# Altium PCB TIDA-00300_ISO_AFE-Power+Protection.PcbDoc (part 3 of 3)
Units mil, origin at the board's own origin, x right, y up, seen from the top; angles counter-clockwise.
Board outline 3622.05 x 2204.8 mil, 4 copper layers (Top Layer, GND Layer, PWR Layer, Bottom Layer), stack 63.6 mil thick; 240 components, 107 nets, 584 pads, 225 vias.
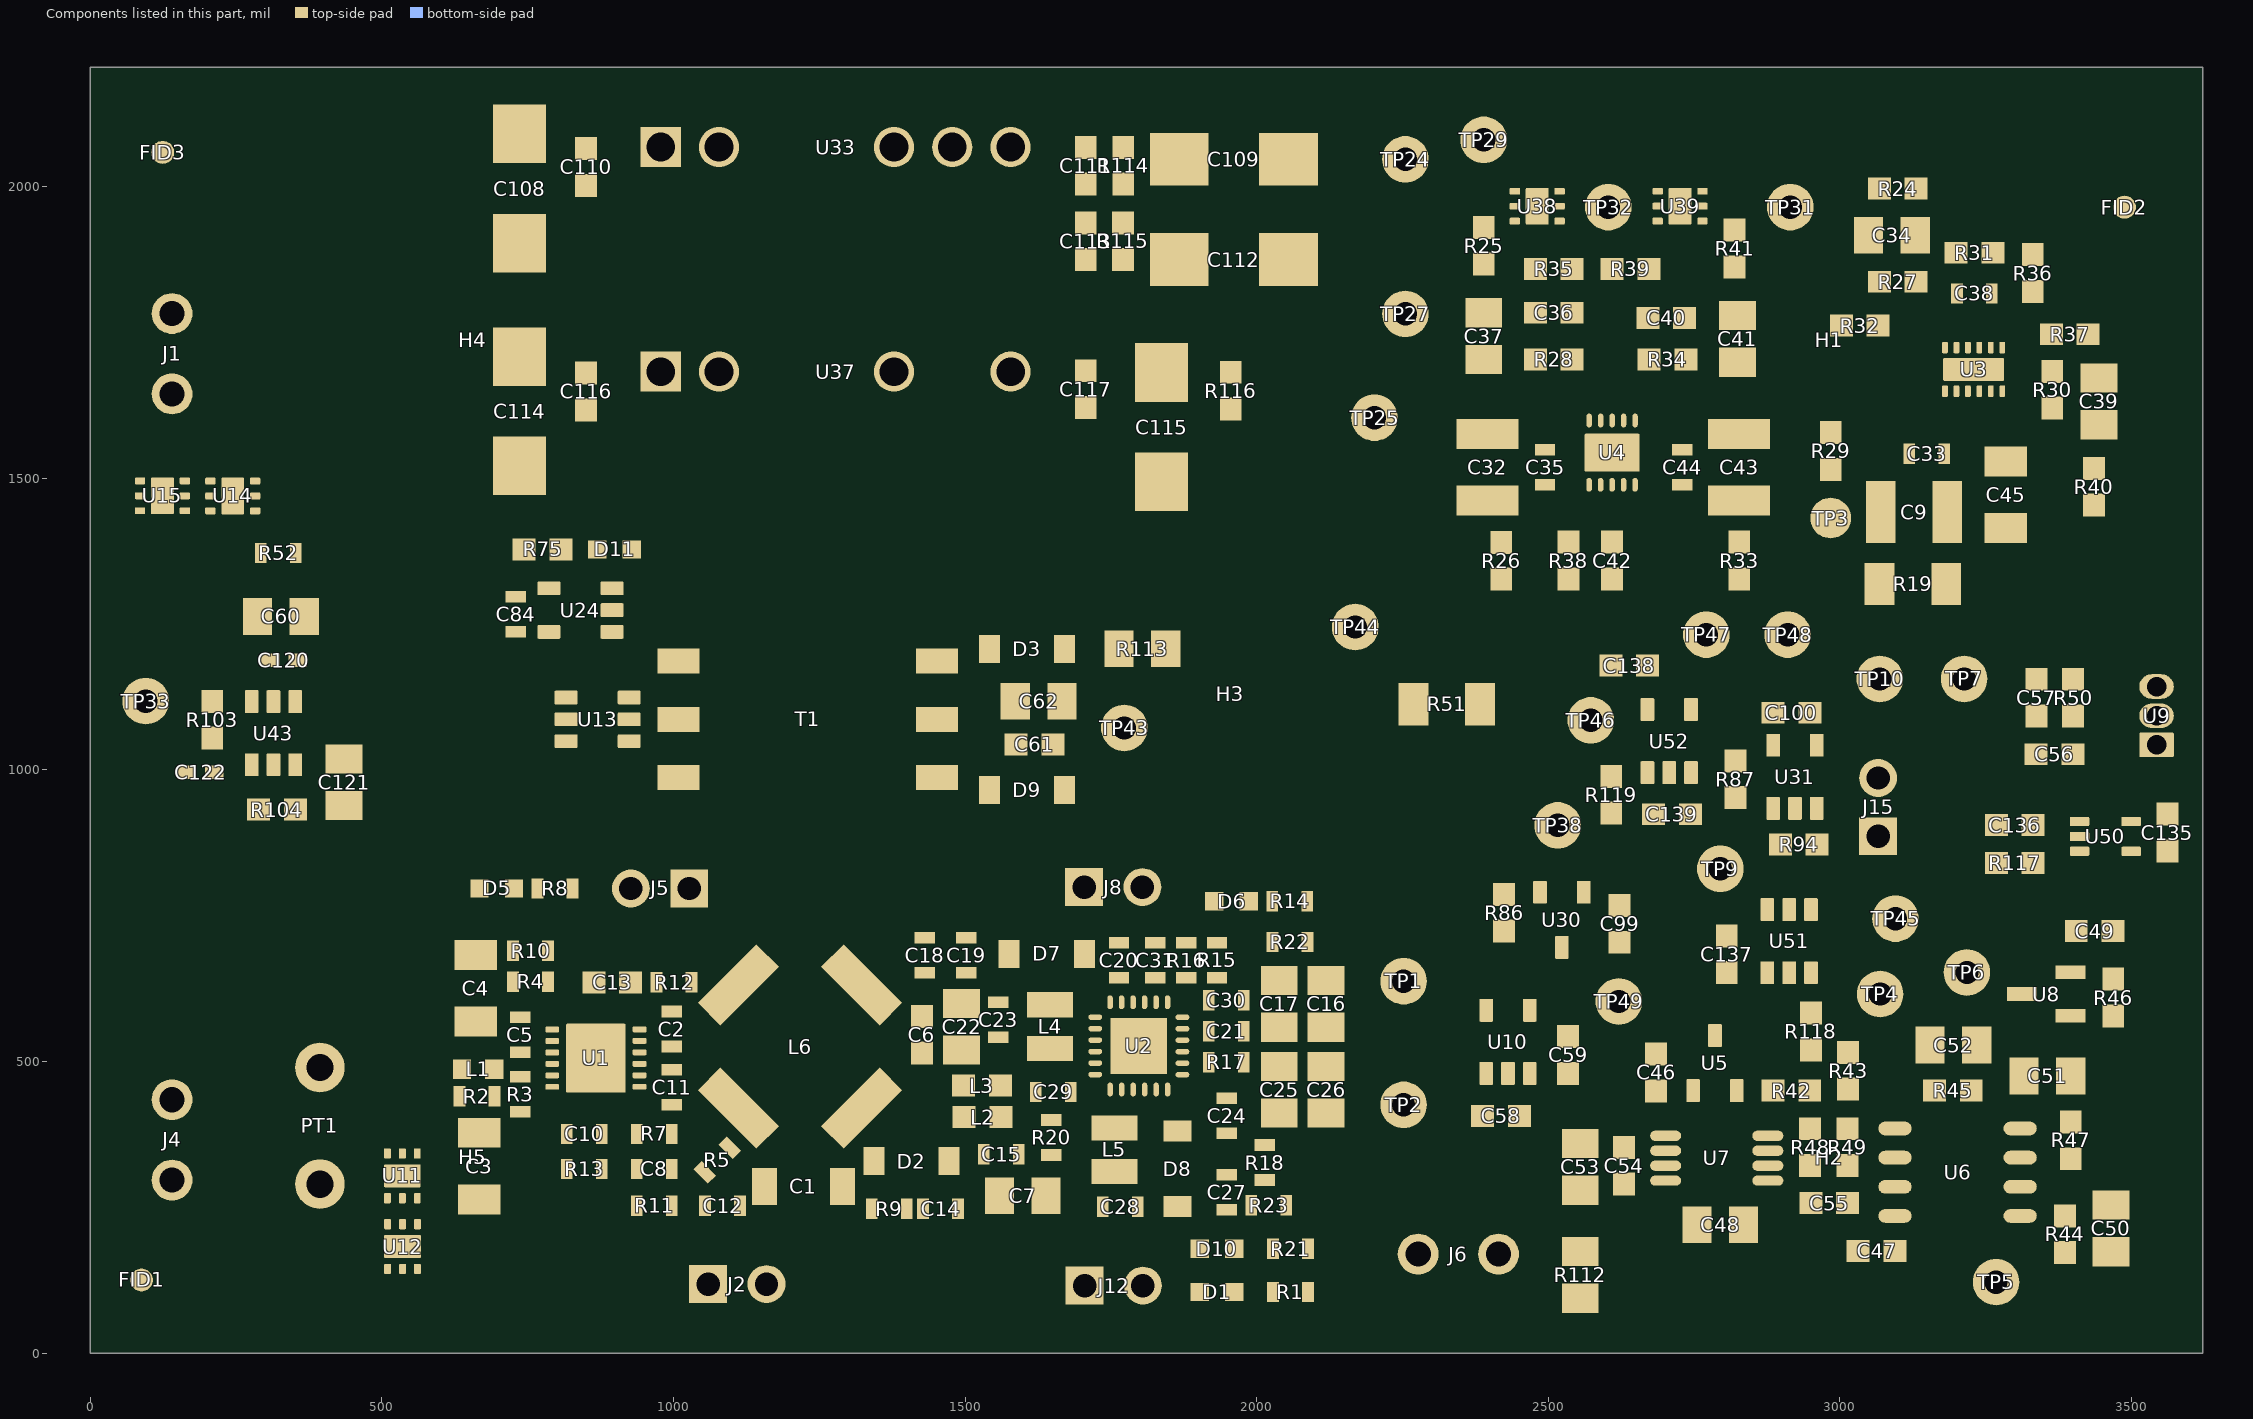
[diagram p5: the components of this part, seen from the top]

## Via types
v1: diameter 24, hole 12, Top Layer to Bottom Layer, tented both sides, 165 vias
v2: diameter 19.68, hole 7.87, Top Layer to Bottom Layer, 27 vias
v3: diameter 32, hole 16, Top Layer to Bottom Layer, tented both sides, 19 vias
v4: diameter 20, hole 8, Top Layer to Bottom Layer, tented both sides, 12 vias
v5: diameter 32, hole 20, Top Layer to Bottom Layer, tented both sides, 2 vias

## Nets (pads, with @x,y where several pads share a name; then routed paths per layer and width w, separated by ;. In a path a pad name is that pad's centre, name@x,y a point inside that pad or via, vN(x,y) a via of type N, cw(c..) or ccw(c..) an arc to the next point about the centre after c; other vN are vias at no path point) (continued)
pads on no net: FID1.1 FID2.1 FID3.1 H1.0 H2.0 H3.0 H4.0 H5.0 U2.7 U2.12 U2.20 U3.13@3202.43,1686.82 U3.13@3256.29,1686.82 U7.1 U7.3 U7.7 U7.8 U8.3 U10.4 U10.5 U11.7@517.28,303.99 U11.7@552.72,303.99 U12.7@517.57,182.72 U12.7@553,182.72 U14.7@244.15,1452.03 U14.7@244.15,1487.46 U15.7@123.61,1452.28 U15.7@123.61,1487.71 U24.1 U24.3 U38.7@2481,1948.93 U38.7@2481,1984.36 U39.7@2726,1948.99 U39.7@2726,1984.43 U50.1 U50.5

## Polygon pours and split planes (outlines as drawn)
NetU11_1 on Bottom Layer "Top Layer-No Net" (solid, pour order 84): 562.78,313.32 504.78,313.32 501.78,310.32 501.78,165.32 503.78,163.32 564.78,163.32 567.78,166.32 567.78,309.32 563.78,313.32
NetU14_1 on Bottom Layer "Top Layer-No Net" (solid, pour order 90): 254.09,1442.37 254.09,1500.37 251.09,1503.37 106.09,1503.37 104.09,1501.37 104.09,1440.37 107.09,1437.37 250.09,1437.37 254.09,1441.37
NetJ4_1 on Bottom Layer "Top Layer-No Net" (solid, pour order 118): 128,396.72 365,396.72 435,466.72 439,470.72 439,507.72 439,510.72 414,535.72 374,535.72 355,516.72 310,471.72 141,471.72 113,471.72 101,459.72 101,410.72 115,396.72
-12V on Bottom Layer "net" (solid, remove dead copper, pour order 392): 2701,2016.4 2705,2020.4 2705,2020.99 3409,2020.99 3552,1877.99 3552,1485.99 3552,1390.99 3533,1371.99 3382,1371.99 3368,1385.99 3368,1822.99 3286,1904.99 2859.8,1904.99 2710.6,1904.99 2701,1914.59
+3.3V on Bottom Layer "net" (solid, remove dead copper, pour order 394): 2519,868.99 2906,1255.99 3085,1255.99 3565,1255.99 3599,1221.99 3599,110.99 3547,58.99 3537.72,49.72 2532.28,49.72 2519,62.99
AGND on Bottom Layer "net" (solid, remove dead copper, pour order 410): 2334,2093.99 2334,2143.99 2352,2161.99 3550,2161.99 3577,2134.99 3599,2112.99 3599,1221.99 3599,110.99 3537.72,49.72 2381,49.72 2359,71.72 2334,96.72 2334,1459.99
GND on Bottom Layer "net" (solid, remove dead copper, pour order 450): 26.51,70.21 26.51,2089.51 81,2143.99 101,2163.99 1096,2163.99 1115,2144.99 1115,1432.72 1115,844.72 1182,777.72 1182,50.72 46,50.72
GND_ISO on Bottom Layer "net" (solid, remove dead copper, pour order 452): 1257,77.72 1257,756.72 1342,841.72 1342,1433.99 1342,2123.99 1380,2161.99 2293,2161.99 2310,2144.99 2310,743.72 2310,72.72 2288,50.72 1284,50.72
NetJ1_1 on Top Layer "net" (solid, remove dead copper, pour order 502): 114.78,1738.94 237.05,1738.94 246,1729.99 274.49,1701.51 274.49,1500.37 274.49,1349.51 278,1345.99 302.89,1345.99 315,1345.99 318,1348.99 318,1409.99 348,1439.99 361,1452.99 361,1649.99 361,1798.99 334,1825.99 325,1834.99 118,1834.99 99,1834.99 93,1828.99 88,1823.99 88,1756.99 88,1744.99 94,1738.99 94.05,1738.94 114.78,1738.94
EXT_5V on Top Layer "net" (solid, remove dead copper, pour order 476): 335,1024.99 335,891.99 342,884.99 525,884.99 699.72,1059.72 778,1059.72 794.74,1076.46 820.22,1076.46 958.26,1076.46 971,1063.72 1045,1063.72 1047,1065.72 1047,1107.72 1045,1109.72 971,1109.72 962,1100.72 791.85,1100.72 776.85,1115.72 643.72,1115.72 615,1144.44 615,1635.99 626,1646.99 636,1656.99 855,1656.99 885,1656.99 894,1647.99 1013,1647.99 1016,1650.99 1016,1755.99 1009,1762.99 622,1762.99 611,1773.99 611,2029.99 625,2043.99 900,2043.99 914,2029.99 1012,2029.99 1016,2033.99 1016,2138.99 1011,2143.99 552,2143.99 521,2112.99 521,1002.99 488,969.99 399,969.99 381,987.99 381,1024.43 370.93,1034.5 339.5,1034.5 335,1029.99
NetC60_1 on Top Layer "net" (solid, remove dead copper, pour order 474): 340,1367.99 340,1092.99 345,1087.99 392,1087.99 400,1095.99 404,1099.99 404,1240.99 404,1390.99 398,1396.99 345,1396.99 340,1391.99
GND on Top Layer "net" (solid, remove dead copper, pour order 472): 27,1466.99 27,1630.99 61,1664.99 78,1681.99 139,1681.99 168,1681.99 176,1673.99 180,1669.99 180,1630.99 180,1619.99 120,1559.99 96,1535.99 96,1496.99 96,1398.99 86,1388.99 37,1388.99 27,1398.99
-12V on Top Layer "net" (solid, remove dead copper, pour order 380): 2967,1914.99 2967,2009.99 2956,2020.99 2720,2020.99 2712,2012.99 2712,1913.99 2721,1904.99 2957,1904.99
GND on Top Layer "TOP_LAYER_GND_P150" (solid, remove dead copper, pour order 150): 596.85,715.72 1178,715.72 1178,235.72 596.85,235.72
NetC32_2 on Top Layer "Top Layer-No Net" (solid, pour order 66): 2454.4,1503.91 2440.4,1489.91 2430.4,1489.91 2332.4,1489.91 2328.4,1485.91 2328.4,1377.91 2336.4,1369.91 2440.4,1369.91 2464.4,1393.91 2547.4,1476.91 2547.4,1493.91 2547.4,1499.91 2543.4,1503.91
NetC36_1 on Top Layer "Top Layer-No Net" (solid, pour order 64): 2500.4,1683.91 2500.4,1806.91 2498.4,1808.91 2425.09,1808.91 2409,1824.99 2409,1888.91 2349.4,1888.91 2345.4,1884.91 2339.4,1878.91 2339.4,1759.91 2341.4,1757.91 2435.4,1757.91 2444.4,1748.91 2444.4,1674.91 2504.4,1614.91 2530.4,1614.91 2539.4,1623.91 2539.4,1628.91 2507.4,1660.91 2500.4,1667.91 2500.4,1680.91
NetC40_2 on Top Layer "Top Layer-No Net" (solid, pour order 62): 2636.4,1805.91 2650.4,1819.91 2650.4,1868.91 2650.4,1877.91 2653.4,1880.91 2692.4,1880.91 2695.4,1877.91 2695.4,1684.91 2654.4,1643.91 2644.4,1643.91 2636.4,1651.91
NetC40_1 on Top Layer "Top Layer-No Net" (solid, pour order 60): 2715.4,1684.91 2715.4,1872.91 2725.4,1882.91 2726.4,1883.91 2855.4,1883.91 2872.4,1883.91 2878.4,1877.91 2878.4,1758.91 2873.4,1753.91 2773.4,1753.91 2767.4,1747.91 2767.4,1661.91 2744.4,1638.91 2709.4,1638.91 2694.4,1623.91 2685.4,1623.91 2678.4,1630.91 2675.4,1633.91 2675.4,1636.91 2715.4,1676.91
AGND on Top Layer "Top Layer-No Net" (solid, pour order 58): 2563.73,1514.47 2549.29,1528.91 2507.4,1528.91 2470.4,1528.91 2450.4,1548.91 2449.4,1549.91 2345.4,1549.91 2339.4,1549.91 2339.4,1726.84 2341.46,1728.91 2418.4,1728.91 2422.4,1724.91 2422.4,1662.91 2503.4,1581.91 2510.4,1574.91 2597.4,1574.91 2685.4,1574.91 2723.4,1612.91 2770.4,1612.91 2784.4,1626.91 2784.4,1720.91 2788.4,1724.91 2880.4,1724.91 2889.4,1715.91 2890.4,1714.91 2890.4,1553.91 2882.4,1545.91 2769.4,1545.91 2753.4,1529.91 2678.4,1529.91 2663.4,1514.91 2662.96,1514.47
NetC43_2 on Top Layer "Top Layer-No Net" (solid, pour order 56): 2764.4,1503.91 2778.4,1489.91 2788.4,1489.91 2886.4,1489.91 2890.4,1485.91 2890.4,1377.91 2882.4,1369.91 2778.4,1369.91 2754.4,1393.91 2671.4,1476.91 2671.4,1493.91 2671.4,1499.91 2675.4,1503.91
NetC36_2 on Top Layer "TOP_LAYER_NETC36_2_P050" (solid, remove dead copper, pour order 50): 2519.4,1868.99 2519.4,1873.99 2524.4,1878.99 2560.32,1878.99 2564.4,1874.91 2564.4,1834.99 2579.4,1819.99 2579.4,1629.46 cw(c2573.99,1638.65) 2574.4,1627.99 2569.4,1628.99 2519.4,1678.99
AGND on Top Layer "TOP_LAYER_AGND_P036" (solid, remove dead copper, pour order 36): 3044.2,1776.98 3044.2,1786.98 3044.2,1791.98 3049.2,1796.98 3084.2,1796.98 3086.38,1796.98 3089.2,1794.16 3089.2,1716.98 3099.2,1706.98 3104.2,1701.98 3194.2,1701.98 3274.2,1701.98 3279.2,1696.98 3279.2,1681.98 3279.2,1676.98 3274.2,1671.98 3104.2,1671.98 3094.2,1661.98 3094.2,1641.98 3094.2,1621.98 3119.2,1596.98 3138.98,1577.2 3138.98,1526.76 3094.2,1481.98 3094.2,1388.72 3090.98,1385.5 3045.98,1385.5 3044.2,1387.28 3044.2,1791.98
NetU14_1 on Top Layer "Top Layer-No Net" (solid, pour order 30): 254.09,1442.37 254.09,1500.37 251.09,1503.37 106.09,1503.37 104.09,1501.37 104.09,1440.37 107.09,1437.37 250.09,1437.37 254.09,1441.37
NetU11_1 on Top Layer "Top Layer-No Net" (solid, pour order 26): 562.78,313.32 504.78,313.32 501.78,310.32 501.78,165.32 503.78,163.32 564.78,163.32 567.78,166.32 567.78,309.32 563.78,313.32
GND_ISO on Top Layer "TOP_LAYER_GND_ISO_P006" (solid, remove dead copper, pour order 6): 1256.85,715.72 2176.85,715.72 2176.85,235.72 1256.85,235.72
NetC39_1 on Top Layer "Top Layer-No Net" (solid, pour order 68): 3305.83,1655.22 3328.83,1655.22 3341.83,1642.22 3385.83,1642.22 3401.83,1626.22 3408.83,1619.22 3429.83,1619.22 3473.83,1619.22 3477.83,1615.22 3477.83,1504.22 3470.83,1497.22 3400.83,1497.22 3391.83,1506.22 3391.83,1540.22 3316.83,1615.22 3296.29,1635.76 3296.29,1645.48
NetC34_1 on Top Layer "Top Layer-No Net" (solid, pour order 70): 3103.83,1939.22 3103.83,1963.22 3109.83,1969.22 3109.83,2018.22 3112.83,2021.22 3149.83,2021.22 3152.83,2018.22 3154.83,2016.22 3154.83,1924.22 3154.83,1792.22 3167.83,1779.22 3189.83,1779.22 3192.83,1776.22 3192.83,1755.22 3188.83,1751.22 3145.83,1751.22 3103.83,1793.22 3103.83,1870.22
NetC9_2 on Top Layer "Top Layer-No Net" (solid, pour order 72): 3155.83,1343.22 3155.83,1567.22 3172.83,1584.22 3194.83,1584.22 3206.83,1596.22 3214.83,1604.22 3214.83,1639.22 3214.83,1657.22 3224.83,1657.22 3224.83,1580.22 3211.83,1567.22 3211.83,1285.22 3206.83,1280.22 3160.83,1280.22 3155.83,1285.22
NetPT1_2 on Top Layer "Top Layer-No Net" (solid, pour order 74): 623,458.72 555,458.72 432,335.72 375,335.72 367,335.72 343,311.72 343,264.72 363,244.72 413,244.72 490,321.72 512,321.72 566,321.72 570,325.72 570,383.61 596.85,410.46 606.11,419.72 632,419.72 647,419.72 650,422.72 650,454.72 646,458.72
NetJ4_1 on Top Layer "Top Layer-No Net" (solid, pour order 100): 128,396.72 365,396.72 435,466.72 439,470.72 439,507.72 439,510.72 414,535.72 374,535.72 355,516.72 310,471.72 141,471.72 113,471.72 101,459.72 101,410.72 115,396.72
GND on Top Layer "Top Layer-No Net" (solid, pour order 120): 597,154.72 307,154.72 258.13,203.59 191.13,270.59 191.13,299.59 191.13,326.59 179.13,338.59 107.13,338.59 103.13,334.59 103.13,246.59 140.13,209.59 274,75.72 494,75.72 599,75.72 604,80.72 604,147.72 597,154.72
GND_ISO on Top Layer "Top Layer-No Net" (solid, pour order 136): 1440,1110.72 1504.85,1110.72 1551.85,1157.72 1609,1157.72 1613,1153.72 1613,1026.72 1609,1022.72 1542,1022.72 1508,1056.72 1504,1060.72 1419,1060.72 1414,1065.72 1414,1107.72 1417,1110.72
+3.3V on Top Layer "Top Layer-No Net" (solid, pour order 140): 2460.55,505.72 2626,505.72 2630,501.72 2630,477.72 2635,472.72 2759,472.72 2764,467.72 2764,429.72 2725,390.72 2725,336.72 2617,336.72 2525,336.72 2519,342.72 2519,441.72 2511,449.72 2468,449.72 2455,462.72 2455,500.17
+5V_IN on Top Layer "Top Layer-No Net" (solid, pour order 142): 3093.98,1275.22 2990.98,1275.22 2984.98,1281.22 2984.98,1355.22 2989.98,1360.22 3092.98,1360.22 3097.98,1355.22 3097.98,1279.22
AGND on Top Layer "net" (solid, remove dead copper, pour order 382): 2462,2016.99 2471,2025.99 2675,2025.99 2696,2005 2696,1932.86 2673.13,1909.99 2479,1909.99 2462,1926.99
+12V on Top Layer "net" (solid, remove dead copper, pour order 384): 2339.4,1919.59 2339.4,2099.4 2377,2136.99 3056,2136.99 3087.98,2105.01 3087.98,2035.22 3087.98,1982.97 3081,1975.99 3021,1975.99 3013,1983.99 3013,2024.99 2983,2054.99 2474.8,2054.99 2453,2033.19 2453,1922.9 2440.09,1909.99 2349,1909.99
+14V on Top Layer "net" (solid, remove dead copper, pour order 388): 2389,1348.99 2385,1344.99 2385,1276.99 2391,1270.99 2555,1270.99 2561,1276.99 2561,1345.99 2558,1348.99
GND_ISO on Top Layer "net" (solid, remove dead copper, pour order 396): 1679,1628.99 1729,1628.99 1776,1581.99 1990,1581.99 2001,1570.99 2001,1436.99 1998,1433.99 1994,1429.99 1631,1429.99 1412,1429.99 1352,1489.99 1342,1499.99 1342,1679.99 1342,1700.99 1356,1714.99 1361,1719.99 1384,1719.99 1404,1719.99 1412,1711.99 1415,1708.99 1415,1671.99 1415,1580.99 1446,1549.99 1584.04,1549.99 1663.04,1628.99
GND_ISO on Top Layer "net" (solid, remove dead copper, pour order 398): 2000,2089.99 2000,1987.99 1991,1978.99 1797,1978.99 1795,1980.99 1795,2021.99 1790,2026.99 1684,2026.99 1646,1988.99 1599,1988.99 1534,1988.99 1522,2000.99 1522,2093.99 1510,2105.99 1453,2105.99 1442,2094.99 1442,1951 1477.01,1915.99 1734,1915.99 1782,1915.99 1786,1919.99 1788,1921.99 1788,1936.99 1795,1943.99 1992,1943.99 2000,1935.99 2000,1830.99 2006,1824.99 2108,1824.99 2129,1845.99 2220,1845.99 2236,1861.99 2236,1979.99 2227,1988.99 2139,1988.99 2129,1998.99 2129,2088.99 2123,2094.99 2004,2094.99 2000,2090.99
GND on Top Layer "net" (solid, remove dead copper, pour order 402): 871,2021.99 826,2021.99 817,2012.99 778,1973.99 694,1973.99 679,1973.99 666,1960.99 666,1821.99 672,1815.99 865,1815.99 1026,1815.99 1115,1904.99 1115,2057.99 1115,2094.99 1106,2103.99 1049,2103.99 1047,2101.99 1041,2095.99 1041,2059.99 1041,2031.99 1041,1970.99 1020,1949.99 887,1949.99 879,1957.99 879,2016.99 874,2021.99
GND on Top Layer "net" (solid, remove dead copper, pour order 404): 871,1636.99 826,1636.99 817,1627.99 778,1588.99 694,1588.99 679,1588.99 666,1575.99 666,1436.99 672,1430.99 865,1430.99 1026,1430.99 1115,1519.99 1115,1672.99 1115,1709.99 1106,1718.99 1049,1718.99 1047,1716.99 1041,1710.99 1041,1674.99 1041,1646.99 1041,1585.99 1020,1564.99 887,1564.99 879,1572.99 879,1631.99 874,1636.99
+5V_IN on Top Layer "vd" (solid, remove dead copper, pour order 562): 2499,367.99 2499,399.24 2444,454.24 2444,501.41 2441.12,504.29 2440.41,503.58 2439.28,504.72 2423,504.72 2418,499.72 2418,455.99 2430.54,443.46 2430.54,236.46 2451.5,215.49 2525,141.99 2627,141.99 2636,150.99 2636,188.99 2589,235.99 2510,235.99 2499,246.99
NetC61_1 on Top Layer "vd" (solid, remove dead copper, pour order 564): 1638,918.72 1638,1243.72 1646,1251.72 1780.28,1251.72 1789,1242.99 1789,1135.99 1822,1102.99 1826,1098.99 1826,1019.99 1826,929.99 1805,908.99 1734.28,908.99 1734,908.72 1648,908.72 1638,918.72
+5V_IN on Top Layer "vd" (solid, remove dead copper, pour order 566): 1888,1164.99 1826,1164.99 1817,1173.99 1817,1305.99 1824,1312.99 1953,1312.99 1962,1303.99 1962,1178.99 1948,1164.99
GND_ISO on GND Layer "net" (solid, remove dead copper, pour order 454): 1257,77.72 1257,756.72 1342,841.72 1342,1433.99 1342,2123.99 1380,2161.99 2293,2161.99 2310,2144.99 2310,743.72 2310,72.72 2288,50.72 1284,50.72
GND on GND Layer "net" (solid, remove dead copper, pour order 456): 26.51,70.21 26.51,2089.51 81,2143.99 101,2163.99 1096,2163.99 1115,2144.99 1115,1432.72 1115,844.72 1182,777.72 1182,50.72 46,50.72
AGND on GND Layer "net" (solid, remove dead copper, pour order 458): 2334,2093.99 2334,2143.99 2352,2161.99 3550,2161.99 3577,2134.99 3599,2112.99 3599,1221.99 3599,110.99 3537.72,49.72 2381,49.72 2359,71.72 2334,96.72 2334,1459.99
+5V_IN on PWR Layer "vd" (solid, remove dead copper, pour order 532): 1257,77.72 1257,756.72 1342,841.72 1342,2123.99 1380,2161.99 3550,2161.99 3599,2112.99 3599,110.99 3537.72,49.72 3536.72,50.72 1284,50.72
NetJ4_1 on PWR Layer "net" (solid, remove dead copper, pour order 462): 26.51,70.21 26.51,2089.51 81,2143.99 101,2163.99 1096,2163.99 1115,2144.99 1115,1432.72 1115,844.72 1182,777.72 1182,50.72 46,50.72

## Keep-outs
Keep-Out Layer:
  lines w10: 0,0 0,2204.72 3622.05,2204.72 3622.05,-0.07
  text ".Layer_Name" at 179.39,-3525.08 h60

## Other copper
Top Layer:
  text ".Layer_Name" at 179.39,-3525.08 h60
GND Layer:
  text ".Layer_Name" at 198,-3518.01 h40
PWR Layer:
  text ".Layer_Name" at 211,-3520.01 h40
Bottom Layer:
  text ".Layer_Name" at 179.39,-3525.08 h60

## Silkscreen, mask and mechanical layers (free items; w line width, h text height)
Top Overlay:
  circle w10: c1958,1124.99 r27.89
  circle w10: c2147,335.99 r27.89
  lines w6: 1682,1035.99 1706,1035.99 1733,1008.99 ; 1900,627.99 1898,625.99 1898,461.99 1980.57,461.99 1991,451.57 1991,377.99 1991.28,377.72 1998.85,377.72 ; 1936,1091.99 1936,911.99 2124,911.99 2124,1141.99 1998,1141.99 ; 1971,635.99 1996.13,635.99 1998.85,638.72 ; 1998.85,672.72 2007.13,680.99 2176,680.99 2184,672.99 2184,353.99 ; 2038.85,371.14 2047,362.99 2096,362.99 2096,286.99 2181,286.99 ; 2317,1836.98 2325.98,1827.99 2338,1827.99 2445.62,1827.99 2449.42,1831.79 ; 2909,267.99 2909,285.99 2915.21,292.2 2920.26,292.2 ; 3042,401.68 3055.18,401.68 3062,408.5 3062,418.99
  lines w10: 602,287.99 602,214.99 1302,214.99 ; 602,359.99 602,398.99 ; 602,516.99 602,589.99 ; 602,658.99 602,735.99 1713,735.99 ; 1514,214.99 1558,214.99 ; 1647,214.99 1890,214.99 ; 1999,214.99 2192,214.99 2192,735.99 2111,735.99
  text "+12V" at 2334,2143.99 h25
  text "AGND" at 2549,2072.99 h25
  text "-12V" at 2867,2029.99 h25
  text "+15V_IN_ISO" at 2088,1954.99 h25
  text "-15V_IN_ISO" at 2040,1689.99 h25
  text "+5V_IN_ISO" at 2055,1509.99 h25
  text "AFE ISO POWER" at 1046,1320.99 h40
  text "TEMP_OUT" at 3112,1220.99 h25
  text "WDI" at 3035,1216.99 h25
  text "+5V_IN" at 1962,1214.99 h25
  text "A" at 1947,1113.99 h25
  text "+14V" at 2213,705.99 h25
  text "-14V" at 2213,488.99 h25
  text "A" at 2139,324.99 h25
  text "REF_2.5V" at 3030,57.99 h25
  text ".Layer_Name" at 179.39,-3525.08 h60
Bottom Overlay:
  text "TIDA-00300_ISO_AFE-Power + Protection" at 1734,1333.99 h40
  text ".Layer_Name" at 179.39,-3525.08 h60
Top Paste:
  text ".Layer_Name" at 179.39,-3525.08 h60
Bottom Paste:
  text ".Layer_Name" at 179.39,-3525.08 h60
Top Solder:
  text ".Layer_Name" at 179.39,-3525.08 h60
  text ".Layer_Name" at 179.39,-3525.08 h60
Bottom Solder:
  text ".Layer_Name" at 179.39,-3525.08 h60
Drill Guide:
  text ".Layer_Name" at 179.39,-3525.08 h60
M1 Board Outline:
  the board outline again, w10
M2 Board Dimensions:
  rectangle: -272.61,-3066.59 102.39,-2941.59
  rectangle: -397.61,-2941.59 -272.61,-2816.59
  lines w7: -397.61,-2941.59 602.39,-2941.59 ; -272.61,-3066.59 -272.61,-2816.59 ; -147.61,-3066.59 -147.61,-2816.59 ; 102.39,-3066.59 102.39,-2816.59 ; 352.39,-3066.59 352.39,-2816.59 ; -397.61,-3066.59 -397.61,-2816.59 602.39,-2816.59 602.39,-3066.59 -397.61,-3066.59
M3 3D STEP Top:
  text ".Layer_Name" at 179.39,-3525.08 h60
M4 3D STEP Bottom:
  text ".Layer_Name" at 179.39,-3525.08 h60
M5 Assembly Top:
  circle w10: c2670.25,978.99 r5.39
  circle w6: c3394.68,911.99 r6.32
  circle w10: c913,1235.99 r5.39
  circle w10: c2886,918.99 r5.39
  circle w10: c3543,1042.99 r5.39
  circle w10: c2561.25,807.99 r5.39
  circle w10: c3389.8,578.32 r5.39
  circle w10: c2746.61,488.99 r5.39
  circle w10: c2390.61,518.99 r5.39
  lines w6: 3326.29,673.99 3432,673.99 3432,556.99 3326.62,556.99 3326.62,674.44 3326.29,674.77
  lines w10: -689.61,-3596.76 5910.39,-3596.76 ; -689.61,-3393.42 5912.39,-3393.42 ; -689.61,-3190.09 -689.61,-3800.09 3315.39,-3800.09 5912.39,-3800.09 5912.39,-3190.09 -689.11,-3190.09 -689.11,-3800.09 886.39,-3800.09 ; 1775.39,-3800.09 1775.39,-3190.09 ; 3042.39,-3393.42 3042.39,-3190.09 ; 3882.39,-3393.42 3882.39,-3190.09 ; 4504.39,-3806.59 4504.39,-3603.76
  text "COMPONENTS MARKED 'DNP' SHOULD NOT BE POPULATED." at 755.89,-2985.09 h20
  text "ASSEMBLY VARIANT:" at 755.39,-3100.59 h20
  text ".VariantName" at 1791.39,-3100.59 h20
  text ".PRJ_Number" at 2057,-3321 h20
  text "PCB VIEWED FROM TOP SIDE" at -626.11,-3322.26 h20
  text "BOARD #:" at 1850.39,-3322.26 h20
  text "REV:" at 3240.39,-3322.26 h20
  text ".PCB_Rev" at 3335,-3323 h20
  text "SVN REV:" at 4078.39,-3322.26 h20
  text ".VersionControl_RevNumber" at 4584.39,-3322.26 h20
  text ".Layer_Name" at 181,-3520.01 h20
  text "LAYER NAME =" at -626.11,-3525.08 h20
  text "TID #:" at 1850.39,-3525.59 h20
  text ".TID" at 1984,-3526 h20
  text "PLOT NAME =" at -626.11,-3730.92 h20
  text ".plot_File_Name" at 179.39,-3730.92 h20
  text "GENERATED    :" at 1852.39,-3730.92 h20
  text ".Print_Date" at 2721.89,-3730.92 h20
  text ".Print_Time" at 3450.89,-3730.92 h20
  text "TEXAS INSTRUMENTS" at 4715.39,-3730.92 h20
M6 Assembly Bottom:
  lines w10: -690.11,-3393.92 5911.89,-3393.92 ; -688.11,-3597.26 5911.89,-3597.26 ; 717.89,-3807.09 717.89,-3604.26 ; 1339.89,-3393.92 1339.89,-3190.59 ; 2179.89,-3393.92 2179.89,-3190.59 ; 3446.89,-3800.59 3446.89,-3190.59 ; 4335.89,-3800.59 5911.39,-3800.59 5911.39,-3190.59 -690.11,-3190.59 -690.11,-3800.59 1906.89,-3800.59 5911.89,-3800.59 5911.89,-3190.59
  text "COMPONENTS MARKED 'DNP' SHOULD NOT BE POPULATED." at 5704.39,-2984.59 h20
  text ".VariantName" at 4660.39,-3100.59 h20
  text "ASSEMBLY VARIANT:" at 5699.39,-3100.59 h20
  text ".PRJ_Number" at 3188.39,-3319.76 h20
  text ".VersionControl_RevNumber" at 637.89,-3322.76 h20
  text "SVN REV:" at 1143.89,-3322.76 h20
  text ".PCB_Rev" at 1879.39,-3322.76 h20
  text "REV:" at 1981.89,-3322.76 h20
  text "BOARD #:" at 3371.89,-3322.76 h20
  text "PCB VIEWED FROM BOTTOM SIDE" at 5848.39,-3322.76 h20
  text ".TID" at 3231.39,-3521.09 h20
  text "TID #:" at 3371.89,-3526.09 h20
  text "TEXAS INSTRUMENTS" at 506.89,-3731.42 h20
  text ".Print_Time" at 1771.39,-3731.42 h20
  text ".Print_Date" at 2500.39,-3731.42 h20
  text "GENERATED    :" at 3369.89,-3731.42 h20
  text ".plot_File_Name" at 5042.89,-3731.42 h20
  text "PLOT NAME =" at 5848.39,-3731.42 h20
M9 Title Sheet:
  drawing of 57 lines, arcs and shapes, not listed
  text "1" at 342.22,5369.91 h70
  text "2" at 2837.89,5369.91 h70
  text "3" at 5327.23,5369.91 h70
  text "4" at 7833.9,5369.91 h70
  text "5" at 10332.89,5369.91 h70
  text "6" at 12837.89,5369.91 h70
  text "A" at -814.11,4226.91 h70
  text "A" at 13985.89,4226.91 h70
  text "A" at 13987.91,4226.13 h70
  text "B" at -814.11,1846.91 h70
  text "B" at 13985.89,1846.91 h70
  text "B" at 13987.91,1846.13 h70
  text "C" at -814.11,-528.09 h70
  text "C" at 13985.89,-528.09 h70
  text "C" at 13987.91,-528.87 h70
  text "PROJECT TITLE:" at 10945.89,-2389.09 h45
  text ".PRJ_Title" at 10995.89,-2522.42 h70
  text "DESIGNED FOR:" at 10945.89,-2690.09 h45
  text ".PRJ_Customer" at 10995.89,-2830.09 h70
  text "D" at -814.11,-2898.09 h70
  text "D" at 13985.89,-2898.09 h70
  text "FILE NAME:" at 10945.89,-2990.09 h45
  text ".PCB_File_Name_No_Path" at 10995.89,-3110.09 h70
  text "Texas Instruments (TI) and/or its licensors do not warrant the accuracy or completeness of this specification" at 5976.39,-3271.93 h45
  text "ENGINEER:" at 10945.89,-3280.09 h45
  text "LAYOUT BY:" at 12450.89,-3280.09 h45
  text "or any information contained therein. TI and/or its licensors do not warrant that this design will meet" at 5931.4,-3384.59 h45
  text ".PRJ_Engineer" at 10995.89,-3435.08 h70
  text ".PCB_Layout" at 12501.39,-3435.08 h70
  text "the specifications, will be suitable for your application or fit for any particular purpose, or will operate in" at 5931.4,-3497.26 h45
  text "ALTIUM DESIGNER VERSION:" at 12450.89,-3590.09 h45
  text "an implementation. TI and/or its licensors do not warrant that the design is production worthy. You should" at 5931.4,-3609.92 h45
  text "completely validate and test your design implementation to confirm the system functionality for your application." at 5976.39,-3722.59 h45
  text ".print_Scale" at 10995.89,-3723.42 h70
  text ".Application_BuildNumber" at 12501.39,-3723.42 h70
  text "1" at 342.22,-3930.09 h70
  text "2" at 2837.89,-3930.09 h70
  text "3" at 5327.23,-3930.09 h70
  text "4" at 7833.9,-3930.09 h70
  text "5" at 10332.89,-3930.09 h70
  text "6" at 12837.89,-3930.09 h70
M10 Fab Notes:
  drawing of 227 lines, arcs and shapes, not listed
  text "DESIGN INFORMATION" at 11973.86,4133.35 h60
  text "(REFER ALSO ARRAY/PANEL PROFILING INFORMATION)" at 11622.35,3967.28 h60
  text "BOARD SIZE" at 10936.35,3962.99 h60
  text "92MM" at 11412.37,3848.63 h60
  text "X" at 11904.35,3835.17 h60
  text "56MM" at 12111,3833.99 h60
  text "Number of Layers :" at 11339.34,3637.99 h60
  text "4" at 12411.89,3632.99 h60
  text "8" at 12412.82,3501.2 h60
  text "MIN. TRACK WIDTH:" at 11339.34,3498.99 h60
  text "MIL" at 12590.34,3498.99 h60
  text "MIN. CLEARANCE:" at 11339.34,3366.99 h60
  text "8" at 12433.37,3367.63 h60
  text "MIL" at 12590.34,3366.99 h60
  text "MIN. VIA DRILL SIZE:" at 11339.34,3234.99 h60
  text "7.874" at 12277.82,3235.2 h60
  text "MIL" at 12590.34,3234.99 h60
  text "6 MIL ( 0.1524 mm)" at 12034.35,3093.28 h60
  text "MINIMUM ANNULAR RING" at 11010.11,3089 h60
  text "EXTERNAL" at 12925.89,3077.99 h60
  text "PER" at 11210.11,2971 h60
  text "IPC-D-275 CLASS 2 LEVEL C" at 11430.11,2970.99 h60
  text "+/-" at 12525.89,2858 h60
  text "MIL, HOLES" at 12918.34,2858.71 h60
  text "+/-" at 13379.89,2858 h60
  text "REGISTRATION TOLERANCES:" at 11010.11,2852.99 h60
  text "METAL" at 12209.89,2852.99 h60
  text "5" at 12786.09,2853 h60
  text "3" at 13619.09,2853 h60
  text "MIL" at 13735.34,2852.99 h60
  text "MATERIAL:" at 10935.35,2643.54 h60
  text "FR-4 High Tg" at 11921.79,2503.2 h60
  text "X" at 11762.89,2494.99 h60
  text "FR-408" at 11356.35,2494.63 h60
  text "OTHER" at 12844.35,2494.63 h60
  text "63 MIL (1.6mm) +/-10%" at 11676.45,2331.92 h60
  text "THICKNESS:" at 11010.11,2327.63 h60
  text "X" at 11548.28,2327.63 h60
  text "OTHER" at 12961.35,2327.63 h60
  text "TOLERANCE:" at 11010.11,2169.63 h60
  text "X" at 11849.42,2169.63 h60
  text "ANSI IPC-6012 TYPE 3 CLASS 2" at 12036.36,2169.63 h60
  text "OTHER +/-" at 12036.35,2013.63 h60
  text "BOW & TWIST:" at 11010.11,1856.63 h60
  text "X" at 11849.42,1856.63 h60
  text "ANSI IPC-6012 TYPE 3 CLASS 2" at 12036.36,1856.63 h60
  text "OTHER +/-" at 12036.35,1698.13 h60
  text "COPPER THICKNESS (FINISHED):" at 10935.35,1562.63 h60
  text "1.4MIL (1oz)" at 11815.34,1409.92 h60
  text "2MIL (1.4oz)" at 12582.35,1409.92 h60
  text "2.8MIL (2oz)" at 13309.35,1409.92 h60
  text "OUTER:" at 11292.35,1405.63 h60
  text "X" at 11686.89,1404.99 h60
  text "X" at 11682.89,1254.99 h60
  text "1.4MIL (1oz)" at 11815.34,1252.92 h60
  text "2.8MIL (2oz)" at 12582.35,1252.92 h60
  text "N/A" at 13308.89,1253.28 h60
  text "INNER SIGNAL:" at 11003.26,1248.63 h60
  text "DRILLING:" at 10935.35,1109.63 h60
  text "REFERENCE:" at 11010.11,992.63 h60
  text "X" at 11658.35,992.63 h60
  text "AS SHOWN" at 11845.34,992.63 h60
  text "X" at 12559.35,992.63 h60
  text "NC_DRILL FILES" at 12696.34,992.63 h60
  text "PTH MIN COPPER THICKNESS:" at 11010.11,834.63 h60
  text "X" at 12360.35,834.63 h60
  text "1MIL" at 12497.34,834.63 h60
  text "OTHER" at 12994.35,834.63 h60
  text "BOARD FINISH:" at 10935.35,675.63 h60
  text "SILKSCREEN:" at 11090.57,557.63 h60
  text "X" at 12039.35,557.63 h60
  text "TOP" at 12165.34,557.63 h60
  text "X" at 12549.35,557.63 h60
  text "BOTTOM" at 12676.34,557.63 h60
  text "SILKSCREEN COLOR:" at 11090.57,390.63 h60
  text "X" at 12038.3,390.63 h60
  text "WHITE" at 12165.34,390.63 h60
  text "OTHER" at 12676.34,390.63 h60
  text "SOLDER RESIST COLOR:" at 11090.57,220.63 h60
  text "X" at 11658.31,61.44 h60
  text "GREEN" at 11785.34,61.44 h60
  text "BLUE" at 12376.34,61.44 h60
  text "OTHER" at 12914.35,61.44 h60
  text "IMMERSION GOLD (ENIG)" at 11996.34,-127.08 h60
  text "ENEPIG" at 13333.89,-130.37 h60
  text "SURFACE FINISH:" at 10935.35,-131.37 h60
  text "X" at 11809.4,-131.37 h60
  text "IMM. TIN/SILVER OR EQUIV" at 11264.89,-288.37 h60
  text "OTHER" at 12696.35,-288.37 h60
  text "ARRAY/PANEL:" at 10935.35,-467.37 h60
  text "CUT AND TRIM PER MECH LAYER 1" at 11996.35,-471.65 h60
  text "N.C. ROUTE" at 11996.34,-623.37 h60
  text "X" at 12675.35,-623.37 h60
  text "V. SCORE" at 12862.35,-623.37 h60
  text "CERTIFICATION:" at 10935.35,-760.37 h60
  text "MATERIALS AND WORKMANSHIP FOR ALL PCBS" at 11660.35,-760.37 h60
  text "TO MEET OR EXCEED THE REQUIREMENTS OF:" at 11660.35,-858.37 h60
  text "X" at 11286.85,-994.87 h60
  text "ANSI IPC-A-600F CLASS ->" at 11425.85,-994.87 h60
  text "X" at 13064.9,-994.87 h60
  text "2" at 13183.85,-994.87 h60
  text "1" at 12868.85,-996.37 h60
  text "3" at 13537.85,-996.37 h60
  text "X" at 11288.9,-1154.37 h60
  text "UL 94V-0" at 11425.85,-1154.37 h60
  text "X" at 12100.9,-1154.37 h60
  text "RoHS" at 12237.85,-1154.37 h60
  text "OTHER" at 12882.25,-1154.37 h60
  text "PER ORDER" at 13279.31,-1154.37 h60
  text "VIA TENTING:" at 12152.89,-1288.01 h60
  text "X" at 12915.37,-1291.37 h60
  text "ADDITIONAL REQUIREMENTS:" at 10935.35,-1295.37 h60
  text "YES" at 12702.55,-1297.09 h60
  text "NO" at 13067.36,-1302.31 h60
  text "MICROSECTION:" at 11010.11,-1410.37 h60
  text "YES" at 11915.85,-1410.37 h60
  text "IMPEDANCE CONTROL:" at 12174.89,-1417.01 h60
  text "YES" at 13158.89,-1418.01 h60
  text "X" at 13700.89,-1425.01 h60
  text "NO" at 13534.36,-1435.31 h60
  text "REQUIRED" at 12777.34,-1566.51 h60
  text "BARE BOARD ELEC. TEST:" at 11010.11,-1569.37 h60
  text "NONE" at 12315.85,-1569.37 h60
  text "X" at 12650.35,-1569.37 h60
  text "PER ORDER" at 13369.35,-1569.37 h60
  text "MANUFACTURER'S UL:" at 11010.11,-1726.37 h60
  text "RAIL" at 12175.85,-1730.65 h60
  text "METAL" at 12667.66,-1730.65 h60
  text "X" at 13042.89,-1731.01 h60
  text "SILK" at 13179.34,-1730.65 h60
M11 Gerber Information:
  lines w10: -689.61,-3596.76 5910.39,-3596.76 ; -689.61,-3393.42 5912.39,-3393.42 ; -689.61,-3190.09 -689.61,-3800.09 3315.39,-3800.09 5912.39,-3800.09 5912.39,-3190.09 -689.11,-3190.09 -689.11,-3800.09 886.39,-3800.09 ; 1775.39,-3800.09 1775.39,-3190.09 ; 3042.39,-3393.42 3042.39,-3190.09 ; 3882.39,-3393.42 3882.39,-3190.09 ; 4504.39,-3806.59 4504.39,-3603.76
  text ".PRJ_Number" at 2307,-3312.01 h30
  text "REV:" at 3365.39,-3317.26 h60
  text ".PCB_Rev" at 3656.89,-3317.26 h60
  text "ALL ARTWORK VIEWED FROM TOP SIDE" at -626.11,-3322.26 h60
  text "BOARD #:" at 1850.39,-3322.26 h60
  text "SVN REV:" at 4078.39,-3322.26 h60
  text ".VersionControl_RevNumber" at 4584.39,-3322.26 h60
  text "LAYER NAME =" at -626.11,-3525.08 h60
  text "TID #:" at 1850.39,-3525.59 h60
  text ".TID" at 2395.89,-3525.59 h60
  text "PLOT NAME =" at -626.11,-3730.92 h60
  text ".plot_File_Name" at 179.39,-3730.92 h30
  text "GENERATED    :" at 1852.39,-3730.92 h60
  text ".Print_Date" at 2721.89,-3730.92 h60
  text ".Print_Time" at 3450.89,-3730.92 h60
  text "TEXAS INSTRUMENTS" at 4715.39,-3730.92 h60
M12 Stackup:
  drawing of 295 lines, arcs and shapes, not listed
  text "Layer" at 4090.5,4141.49 h60
  text "Name" at 4500.41,4141.49 h60
  text "Material" at 5430.16,4141.49 h60
  text "Thickness" at 6289.92,4141.49 h60
  text "Constant" at 6939.76,4141.49 h60
  text "Board Layer Stack" at 7509.62,4141.49 h60
  text "1" at 4090.5,4021.49 h60
  text "Top Overlay" at 4500.41,4021.49 h60
  text "2" at 4090.5,3901.49 h60
  text "Top Solder" at 4500.41,3901.49 h60
  text "Solder Resist" at 5430.16,3901.49 h60
  text "0.30mil" at 6289.92,3901.49 h60
  text "3.5" at 6939.76,3901.49 h60
  text "3" at 4090.5,3781.49 h60
  text "Top Layer" at 4500.41,3781.49 h60
  text "Copper" at 5430.16,3781.49 h60
  text "1.40mil" at 6289.92,3781.49 h60
  text "4" at 4090.5,3661.49 h60
  text "Dielectric1" at 4500.41,3661.49 h60
  text "FR-4 High Tg" at 5430.16,3661.49 h60
  text "15.00mil" at 6289.92,3661.49 h60
  text "4.5" at 6939.76,3661.49 h60
  text "5" at 4090.5,3541.49 h60
  text "GND Layer" at 4500.41,3541.49 h60
  text "Copper" at 5430.16,3541.49 h60
  text "1.40mil" at 6289.92,3541.49 h60
  text "6" at 4090.5,3421.49 h60
  text "Dielectric 2" at 4500.41,3421.49 h60
  text "FR-4 High Tg" at 5430.16,3421.49 h60
  text "28.00mil" at 6289.92,3421.49 h60
  text "4.5" at 6939.76,3421.49 h60
  text "7" at 4090.5,3301.49 h60
  text "PWR Layer" at 4500.41,3301.49 h60
  text "Copper" at 5430.16,3301.49 h60
  text "1.40mil" at 6289.92,3301.49 h60
  text "8" at 4090.5,3181.49 h60
  text "Dielectric 3" at 4500.41,3181.49 h60
  text "FR-4 High Tg" at 5430.16,3181.49 h60
  text "15.00mil" at 6289.92,3181.49 h60
  text "4.5" at 6939.76,3181.49 h60
  text "9" at 4090.5,3061.49 h60
  text "Bottom Layer" at 4500.41,3061.49 h60
  text "Copper" at 5430.16,3061.49 h60
  text "1.40mil" at 6289.92,3061.49 h60
  text "10" at 4090.5,2941.49 h60
  text "Bottom Solder" at 4500.41,2941.49 h60
  text "Solder Resist" at 5430.16,2941.49 h60
  text "0.30mil" at 6289.92,2941.49 h60
  text "3.5" at 6939.76,2941.49 h60
  text "11" at 4090.5,2821.49 h60
  text "Bottom Overlay" at 4500.41,2821.49 h60
M13 Component Bodies Top:
  text ".Layer_Name" at 179.39,-3525.08 h60
M14 Component Bodies Bottom:
  text ".Layer_Name" at 179.39,-3525.08 h60
M15 Courtyards Top:
  text ".Layer_Name" at 179.39,-3525.08 h60
M16 Courtyards Bottom:
  text ".Layer_Name" at 179.39,-3525.08 h60
Drill Drawing:
  circle w10: c3879.62,-48.17 r20
  circle w10: c3879.62,-48.17 r33.33
  circle w10: c3879.62,-498.17 r33.33
  lines w10: 3846.29,-681.51 3846.29,-664.84 3862.96,-648.17 3846.29,-631.51 3846.29,-614.84 3862.96,-614.84 3879.62,-631.51 3896.29,-614.84 3912.96,-614.84 3912.96,-631.51 3896.29,-648.17 3912.96,-664.84 3912.96,-681.51 3896.29,-681.51 3879.62,-664.84 3862.96,-681.51 3846.29,-681.51 ; 3846.29,-381.51 3912.96,-381.51 3912.96,-314.84 3846.29,-314.84 3846.29,-381.51 ; 3846.29,-198.17 3879.62,-231.51 3912.96,-198.17 3879.62,-164.84 3846.29,-198.17 ; 3846.29,68.49 3846.29,85.16 3862.96,101.83 3846.29,118.49 3846.29,135.16 3862.96,135.16 3879.62,118.49 3896.29,135.16 3912.96,135.16 3912.96,118.49 3896.29,101.83 3912.96,85.16 3912.96,68.49 3896.29,68.49 3879.62,85.16 3862.96,68.49 3846.29,68.49 ; 3846.29,235.16 3862.96,235.16 3862.96,218.49 3896.29,218.49 3896.29,235.16 3912.96,235.16 3912.96,268.49 3896.29,268.49 3896.29,285.16 3862.96,285.16 3862.96,268.49 3846.29,268.49 3846.29,235.16 ; 3846.29,368.49 3879.62,385.16 3912.96,368.49 3896.29,401.83 3912.96,435.16 3879.62,418.49 3846.29,435.16 3862.96,401.83 3846.29,368.49 ; 3846.29,535.16 3862.96,535.16 3862.96,518.49 3896.29,518.49 3896.29,535.16 3912.96,535.16 3912.96,568.49 3896.29,568.49 3896.29,585.16 3862.96,585.16 3862.96,568.49 3846.29,568.49 3846.29,535.16 ; 3846.29,735.16 3912.96,735.16 3879.62,668.49 3846.29,735.16 ; 3859.62,-668.17 3859.62,-658.17 3869.62,-648.17 3859.62,-638.17 3859.62,-628.17 3869.62,-628.17 3879.62,-638.17 3889.62,-628.17 3899.62,-628.17 3899.62,-638.17 3889.62,-648.17 3899.62,-658.17 3899.62,-668.17 3889.62,-668.17 3879.62,-658.17 3869.62,-668.17 3859.62,-668.17 ; 3859.62,241.83 3869.62,241.83 3869.62,231.83 3889.62,231.83 3889.62,241.83 3899.62,241.83 3899.62,261.83 3889.62,261.83 3889.62,271.83 3869.62,271.83 3869.62,261.83 3859.62,261.83 3859.62,241.83
  lines w15: 3786.5,-726.51 8187.33,-726.51 ; 3786.5,773.49 8187.33,773.49 ; 4337.38,-876.51 4337.38,923.49 ; 4937.22,-876.51 4937.22,923.49 ; 6036.9,-876.51 6036.9,923.49 ; 6542.77,-876.51 6542.77,923.49 ; 7276.57,-876.51 7276.57,923.49 ; 3786.5,-876.51 8187.33,-876.51 8187.33,923.49 3786.5,923.49 3786.5,-876.51
  text "Symbol" at 3876.5,818.49 h72
  text "Count" at 4382.38,818.49 h72
  text "Hole Size" at 4982.22,818.49 h72
  text "Plated" at 6081.9,818.49 h72
  text "Hole Type" at 6587.77,818.49 h72
  text "Hole Length" at 7321.57,818.49 h72
  text "27" at 4382.38,668.49 h60
  text "7.87mil (0.200mm)" at 4982.22,668.49 h60
  text "PTH" at 6081.9,668.49 h60
  text "Round" at 6587.77,668.49 h60
  text "-" at 7321.57,668.49 h60
  text "12" at 4382.38,518.49 h60
  text "8.00mil (0.203mm)" at 4982.22,518.49 h60
  text "PTH" at 6081.9,518.49 h60
  text "Round" at 6587.77,518.49 h60
  text "-" at 7321.57,518.49 h60
  text "165" at 4382.38,368.49 h60
  text "12.00mil (0.305mm)" at 4982.22,368.49 h60
  text "PTH" at 6081.9,368.49 h60
  text "Round" at 6587.77,368.49 h60
  text "-" at 7321.57,368.49 h60
  text "19" at 4382.38,218.49 h60
  text "16.00mil (0.406mm)" at 4982.22,218.49 h60
  text "PTH" at 6081.9,218.49 h60
  text "Round" at 6587.77,218.49 h60
  text "-" at 7321.57,218.49 h60
  text "2" at 4382.38,68.49 h60
  text "20.00mil (0.508mm)" at 4982.22,68.49 h60
  text "PTH" at 6081.9,68.49 h60
  text "Round" at 6587.77,68.49 h60
  text "-" at 7321.57,68.49 h60
  text "3" at 4382.38,-81.51 h60
  text "33.47mil (0.850mm)" at 4982.22,-81.51 h60
  text "PTH" at 6081.9,-81.51 h60
  text "Round" at 6587.77,-81.51 h60
  text "-" at 7321.57,-81.51 h60
  text "33" at 4382.38,-231.51 h60
  text "40.00mil (1.016mm)" at 4982.22,-231.51 h60
  text "PTH" at 6081.9,-231.51 h60
  text "Round" at 6587.77,-231.51 h60
  text "-" at 7321.57,-231.51 h60
  text "6" at 4382.38,-381.51 h60
  text "43.31mil (1.100mm)" at 4982.22,-381.51 h60
  text "PTH" at 6081.9,-381.51 h60
  text "Round" at 6587.77,-381.51 h60
  text "-" at 7321.57,-381.51 h60
  text "2" at 4382.38,-531.51 h60
  text "47.00mil (1.194mm)" at 4982.22,-531.51 h60
  text "PTH" at 6081.9,-531.51 h60
  text "Round" at 6587.77,-531.51 h60
  text "-" at 7321.57,-531.51 h60
  text "9" at 4382.38,-681.51 h60
  text "49.21mil (1.250mm)" at 4982.22,-681.51 h60
  text "PTH" at 6081.9,-681.51 h60
  text "Round" at 6587.77,-681.51 h60
  text "-" at 7321.57,-681.51 h60
  text "278 Total" at 4382.38,-831.51 h60
  text "Drill Table" at 3835.77,-1627.01 h60
  text "FOR 7.874MIL DRILL +0/-7.874MIL" at 3841,-1763.01 h60
  text "FOR 8MIL DRILL +0/-8MIL" at 3838,-1844.01 h60
  text "FOR 10MIL DRILL +0/-10MIL" at 3837,-1926.01 h60
  text "FOR 12MIL DRILL +0/-12MIL" at 3836,-2011.01 h60
  text "FOR 16MIL DRILL +0/-16MIL" at 3835.77,-2100.01 h60
  text "FOR PTH DRILL +/-3MIL" at 3831.51,-2186.56 h60
  text "FOR NPTH DRILL +/-2MIL" at 3835.77,-2270.01 h60
  text ".Layer_Name" at 179.39,-3525.08 h60
M17 Embedded Cavity:
  text ".Layer_Name" at 179.39,-3525.08 h60
M18 Embedded Assembly:
  text ".Layer_Name" at 179.39,-3525.08 h60
M19 Embedded Keepout:
  text ".Layer_Name" at 179.39,-3525.08 h60

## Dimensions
0,0 to 0,2204.72 on M2 Board Dimensions
0,2204.72 to 3622.05,2204.72 on M2 Board Dimensions
-397.61,-3066.59 to 602.39,-3066.59 on M2 Board Dimensions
